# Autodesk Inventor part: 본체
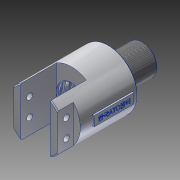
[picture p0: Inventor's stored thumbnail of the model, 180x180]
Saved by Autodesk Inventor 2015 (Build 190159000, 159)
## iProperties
Created: 2019-02
Part Number: 본체
Material: 알루미늄 6061
Document SubType Name: Modeling
Designer: now
Density: 2.7 g/cm^3
Appearance: 알루미늄 - 평지
Mass: 345.889 g
Surface Area: 290.427 cm^2
Volume: 128.107 cm^3
Author: now
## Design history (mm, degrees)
sketch "스케치1"
  geometry: C1 r 13 at (0, 0); 1 further point
  constraints: 1 centre point, 1 coincident
  dimensions: "d1" = 26 diameter of C1
extrude "돌출1" new body sketch "스케치1" distance "d2" = 5; taper "d3" = 0 deg
sketch "스케치2"
  geometry: C1 r 13 at (0, 0) reference; C2 r 15 at (0, 0)
  constraints: 1 centre point, 1 coincident
  dimensions: "d4" = 15 radius of C2
extrude "돌출2" join sketch "스케치2" distance "d5" = 29; taper "d6" = 0 deg
sketch "스케치3"
  geometry: C1 r 13 at (0, 0) reference; C2 r 29 at (0, 0)
  constraints: 1 centre point, 1 coincident
  dimensions: "d7" = 29 radius of C2
extrude "돌출3" join sketch "스케치3" distance "d8" = 38; taper "d9" = 0 deg
feature "스레드1" dims "d10" = 10, "d11" = 0
chamfer "모따기1" distance "d12" = 1; stored, may be unused: second distance "d13" = 2, angle "d14" = 45 deg
sketch "스케치6"
  geometry: L1 (0, -13)-(0, -29) reference; L2 (0, -29)-(-38, -29) reference; L3 (-38, -29)-(-38, 29) reference; L4 (-38, 29)-(0, 29) reference; L5 (0, 29)-(0, 13) reference; L6 (0, 13)-(5, 13) reference; L7 (5, 13)-(5, 15) reference; L8 (5, 15)-(33, 15) reference; L9 (33, 15)-(34, 14) reference; L10 (34, 14)-(34, -14) reference; L11 (34, -14)-(33, -15) reference; L12 (33, -15)-(5, -15) reference; L13 (5, -15)-(5, -13) reference; L14 (5, -13)-(0, -13) reference; L15 (-38, 14)-(-35.35, 14); L16 (-35.35, 14)-(-35.35, 17); L17 (-35.35, 17)-(-30.65, 17); L18 (-30.65, 17)-(-30.65, 14); L19 (-30.65, 14)-(-26.35, 14); L20 (-26.35, 14)-(-26.35, 17); L21 (-26.35, 17)-(-21.65, 17); L22 (-21.65, 17)-(-21.65, 14); L23 (-21.65, 14)-(-18, 14); L24 (-18, 14)-(-18, 16); L25 (-18, 16)-(-11, 16); L26 (-11, 16)-(-11, 0); L27 (-11, 0)-(-38, 0); L28 (-38, 29)-(-38, -29) reference; L29 (-38, 14)-(-38, 0); 5 further points
  constraints: 28 end point, 8 perpendicular, 7 point on line, 3 midpoint, 2 coincident, 2 horizontal, 1 collinear
  dimensions: "d15" = 4.7 distance of L16.end L17.end; "d16" = 4.7 distance of L20.end L21.end; "d17" = 2.35 distance of L16.end point (-33, 17); "d18" = 2.35 distance of L20.end point (-24, 17); "d19" = 9 distance of point (-24, 17) point (-33, 17); "d20" = 5 horizontal distance of L15.start point (-33, 17); "d21" = 28 diameter of L15.start L27; "d22" = 34 diameter of L16.end L27; "d23" = 32 diameter of L25.end L27; "d24" = 7 distance of L24.end L25.end; "d90" = 27 horizontal distance of L15.start L25.end
revolve "회전1" sketch "스케치6" stored, may be unused: angle "d26" = 90 deg
chamfer "모따기2" distance "d27" = 1; stored, may be unused: second distance "d28" = 2, angle "d29" = 45 deg
chamfer "모따기3" distance "d30" = 1; stored, may be unused: second distance "d31" = 2, angle "d32" = 45 deg
sketch "스케치7"
  geometry: C1 r 29 at (0, 0) reference; C2 r 17 at (0, 0) reference; C3 r 29 at (0, 0)
  constraints: 1 centre point, 1 coincident
  dimensions: "d33" = 29 radius of C3
extrude "돌출4" join sketch "스케치7" distance "d34" = 36; taper "d35" = 0 deg
sketch "스케치8"
  geometry: L1 (-15, -38)-(15, -38) reference; L2 (-29, -74)-(29, -74) reference; L3 (-15, -74)-(15, -74); L4 (15, -74)-(15, -38); L5 (15, -38)-(-15, -38); L6 (-15, -38)-(-15, -74); 2 further points
  constraints: 8 end point, 2 midpoint, 2 parallel, 1 horizontal, 1 perpendicular
  dimensions: "d36" = 30 distance of L4.end L5.end; "d37" = 36 distance of L3.end L4.end
extrude "돌출5" cut sketch "스케치8" stored distance "d38" = 36; taper "d39" = 0 deg
sketch "스케치9"
  geometry: L1 (15, 24.819)-(15, -24.819) reference; L2 (22, 0)-(22, -18.894); L3 (22, 0)-(22, 18.894); L4 (22, 18.894)-(22, -18.894); A1 r 29 centre (0, 0) between (15, -24.819) and (15, 24.819) reference; A2 r 18.894 centre (22, 0) between (22, -18.894) and (22, 18.894); 1 further point
  constraints: 6 end point, 4 point on circle, 1 centre point, 1 coincident, 1 horizontal alignment, 1 vertical
  dimensions: "d40" = 7 distance from line of point (22, 0) L1; "d41" = 180 deg angle of L2 L3
extrude "돌출6" cut sketch "스케치9" distance "d42" = 16; taper "d43" = 0 deg
node "작업 평면1"
sketch "스케치11"
  geometry: L1 (0, 28)-(0, -28) reference; L2 (-45, 5)-(-5, 5); L3 (-5, 5)-(-5, -5); L4 (-5, -5)-(-45, -5); L5 (-45, -5)-(-45, 5); 3 further points
  constraints: 8 end point, 2 midpoint, 2 parallel, 1 horizontal, 1 horizontal alignment, 1 perpendicular
  dimensions: "d49" = 5 distance between parallel lines of L1 L3; "d50" = 40 distance of L2.start L2.end; "d51" = 10 distance of L4.end L2.start
extrude "돌출7" join sketch "스케치11" stored distance "d52" = 0; taper "d53" = 0 deg
sketch "스케치12"
  geometry: 4 further points
  constraints: 1 other
  dimensions: "d54" = 20 vertical distance of point (-5, -45) point (0, -25); "d55" = 5 horizontal distance of point (5, -45) point (0, -25)
feature "엠보싱1" sketch "스케치12" dims "d56" = 0.5, "d57" = 0
chamfer "모따기4" distance "d58" = 1; stored, may be unused: second distance "d59" = 2, angle "d60" = 45 deg
sketch "스케치13"
  geometry: L1 (42.538, -16)-(-4.749, -16) reference; L2 (18.894, 58)-(18.894, -16); C1 r 3 at (9.894, -7); C2 r 3 at (27.894, -7); 1 further point
  constraints: 2 centre point, 2 end point, 1 midpoint, 1 other
  dimensions: "d67" = 18 distance of C2.centre C1.centre; "d68" = 6 diameter of C2; "d69" = 9 vertical distance of point (36.215, -16) C2.centre
extrude "돌출8" cut sketch "스케치13" distance "d70" = 15; taper "d71" = 0 deg
chamfer "모따기5" distance "d72" = 1; stored, may be unused: second distance "d73" = 2, angle "d74" = 45 deg
fillet "모깎기1" dims "d75" = 0.8
sketch "스케치14"
  geometry: C1 r 16 at (0, 0) reference
hole "구멍1" sketch "스케치14" at (0, 0) diameter "d76" = 8; stored, may be unused: countersink angle "d80" = 90 deg, drill point angle "d82" = 0 deg; dims "d77" = 6, "d78" = 4, "d79" = 2, "d81" = 23
sketch "스케치15"
  geometry: C1 r 14 at (0, 0) reference
hole "구멍2" sketch "스케치15" at (0, 0) diameter "d83" = 12.376; stored, may be unused: countersink angle "d87" = 90 deg, drill point angle "d89" = 118 deg; dims "d84" = 18, "d85" = 4, "d86" = 2, "d88" = 22
node "솔리드1"
mirror "대칭1"
mirror "대칭2"
node "절단 모서리 투영1"
